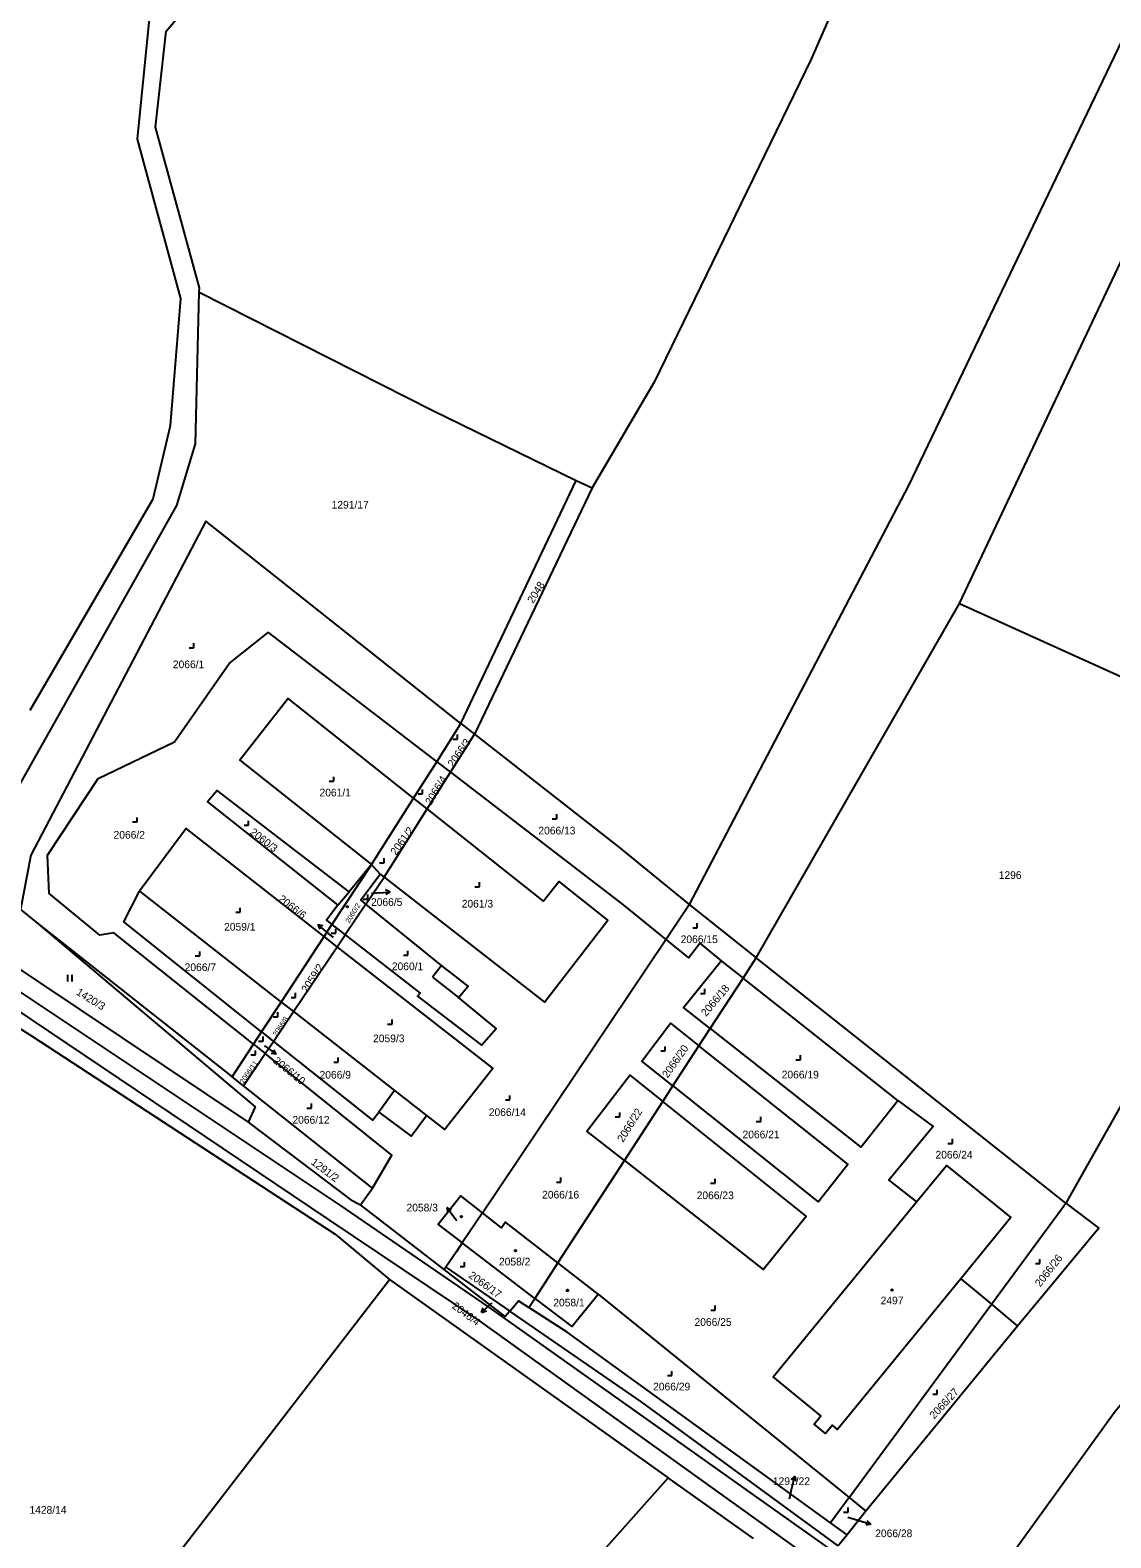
# Model space of a CAD drawing. Extents: x -679220 to -673243, y -1075091 to -1066557.
# Drawn here: x -677836.3 to -677596.9, y -1070402.6 to -1070068.5 of the extents above; entities that cross this region are included whole.
import ezdxf

# ---------------------------------------------------------------- set-up
doc = ezdxf.new("R2010")
doc.units = 0
for name, color, linetype in [('Hranice parcel', 7, 'Continuous'), ('Parcelní čísla', 7, 'Continuous'), ('Pop  PČ popisy', 7, 'Continuous'), ('Vnitřní kresba', 7, 'Continuous'), ('Značky budov', 7, 'Continuous'), ('Značky kultur', 7, 'Continuous')]:
    doc.layers.add(name, color=color, linetype=linetype)

msp = doc.modelspace()

# ---------------------------------------------------------------- linework, layer by layer
at = {"layer": 'Hranice parcel'}
for p, q in [((-677740.82, -1070222.17), (-677715.32, -1070168.27)), ((-677711.74, -1070169.95), (-677737.84, -1070224.53)), ((-677715.32, -1070168.27), (-677711.74, -1070169.95)), ((-677675.39, -1070274.05), (-677630.39, -1070195.53)), ((-677630.39, -1070195.53), (-677551.97, -1070231.11)), ((-677746.2, -1070230.63), (-677740.82, -1070222.17)), ((-677740.82, -1070222.17), (-677737.84, -1070224.53)), ((-677743.16, -1070232.96), (-677737.84, -1070224.53)), ((-677751.31, -1070238.67), (-677746.2, -1070230.63)), ((-677746.2, -1070230.63), (-677743.16, -1070232.96)), ((-677748.29, -1070241.07), (-677743.16, -1070232.96)), ((-677551.97, -1070231.11), (-677606.83, -1070328.42)), ((-677760.67, -1070253.39), (-677751.31, -1070238.67)), ((-677748.29, -1070241.07), (-677751.31, -1070238.67)), ((-677757.85, -1070256.21), (-677748.29, -1070241.07)), ((-677760.67, -1070253.39), (-677769.4, -1070266.7)), ((-677758.72, -1070255.53), (-677760.67, -1070253.39)), ((-677761.86, -1070262.16), (-677757.85, -1070256.21)), ((-677758.72, -1070255.53), (-677757.85, -1070256.21)), ((-677812.04, -1070259.33), (-677780.65, -1070283.87)), ((-677838.43, -1070263.34), (-677834.96, -1070266.14)), ((-677761.86, -1070262.16), (-677766.46, -1070268.99)), ((-677695.46, -1070269.98), (-677690.28, -1070262.25)), ((-677690.28, -1070262.25), (-677675.39, -1070274.05)), ((-677834.96, -1070266.14), (-677791.54, -1070300.48)), ((-677771.13, -1070269.34), (-677769.4, -1070266.7)), ((-677769.4, -1070266.7), (-677766.46, -1070268.99)), ((-677847.48, -1070270.67), (-677787.98, -1070310.51)), ((-677780.65, -1070283.87), (-677771.13, -1070269.34)), ((-677768.23, -1070271.61), (-677771.13, -1070269.34)), ((-677768.23, -1070271.61), (-677766.46, -1070268.99)), ((-677736.08, -1070330.58), (-677695.46, -1070269.98)), ((-677777.93, -1070286), (-677768.23, -1070271.61)), ((-677678.31, -1070278.55), (-677675.39, -1070274.05)), ((-677606.83, -1070328.42), (-677675.39, -1070274.05)), ((-677683.17, -1070274.71), (-677678.31, -1070278.55)), ((-677685.6, -1070289.77), (-677678.31, -1070278.55)), ((-677644.02, -1070305.7), (-677678.31, -1070278.55)), ((-677784.99, -1070290.48), (-677780.65, -1070283.87)), ((-677780.65, -1070283.87), (-677777.93, -1070286)), ((-677782.37, -1070292.58), (-677777.93, -1070286)), ((-677786.8, -1070293.24), (-677784.99, -1070290.48)), ((-677784.99, -1070290.48), (-677782.37, -1070292.58)), ((-677688.09, -1070293.59), (-677685.6, -1070289.77)), ((-677791.54, -1070300.48), (-677786.8, -1070293.24)), ((-677786.8, -1070293.24), (-677784.21, -1070295.31)), ((-677784.21, -1070295.31), (-677782.37, -1070292.58)), ((-677693.85, -1070302.46), (-677688.09, -1070293.59)), ((-677789.03, -1070302.47), (-677784.21, -1070295.31)), ((-677789.03, -1070302.47), (-677791.54, -1070300.48)), ((-677760.41, -1070325.11), (-677789.03, -1070302.47)), ((-677696.09, -1070305.92), (-677693.85, -1070302.46)), ((-677704.6, -1070319.01), (-677696.09, -1070305.92)), ((-677719.33, -1070341.67), (-677704.6, -1070319.01)), ((-677763.09, -1070328.78), (-677760.41, -1070325.11)), ((-677744.51, -1070343.17), (-677763.09, -1070328.78)), ((-677736.08, -1070330.58), (-677740.53, -1070337.23)), ((-677623.32, -1070350.84), (-677606.83, -1070328.42)), ((-677724.43, -1070349.53), (-677740.53, -1070337.23)), ((-677744.15, -1070342.63), (-677744.51, -1070343.17)), ((-677744.15, -1070342.63), (-677730.02, -1070352.35)), ((-677719.33, -1070341.67), (-677724.43, -1070349.53)), ((-677710.43, -1070348.59), (-677719.33, -1070341.67)), ((-677756.66, -1070345.34), (-677694.91, -1070389.28)), ((-677630.06, -1070345.2), (-677623.32, -1070350.84)), ((-677725.76, -1070351.58), (-677724.43, -1070349.53)), ((-677710.43, -1070348.59), (-677654.8, -1070393.66)), ((-677654.8, -1070393.66), (-677623.32, -1070350.84)), ((-677623.32, -1070350.84), (-677617.53, -1070355.69)), ((-677617.53, -1070355.69), (-677651.1, -1070396.66)), ((-677676.01, -1070402.73), (-677694.91, -1070389.28)), ((-677654.8, -1070393.66), (-677658.94, -1070399.28)), ((-677654.8, -1070393.66), (-677651.1, -1070396.66)), ((-677651.1, -1070396.66), (-677655.29, -1070401.92)), ((-677655.29, -1070401.92), (-677658.94, -1070399.28)), ((-677655.29, -1070401.92), (-677657.23, -1070404.36))]:
    msp.add_line(p, q, dxfattribs=at)
for points in [[(-677543.22, -1069801.15), (-677561, -1069854.23), (-677585.31, -1069913.19), (-677593.86, -1069910.68), (-677623.04, -1069982.87), (-677663.22, -1070074.94), (-677697.99, -1070146.52), (-677711.74, -1070169.95)], [(-677490.38, -1069845.96), (-677541.96, -1069957.49), (-677593.5, -1070068.97), (-677641.71, -1070169.41), (-677690.28, -1070262.25)], [(-677630.39, -1070195.53), (-677551.44, -1070028.23), (-677472.53, -1069860.87)], [(-677798.79, -1070126.56), (-677798.76, -1070125.62), (-677808.5, -1070090.03), (-677806.15, -1070068.7), (-677792.35, -1070052.45), (-677770.15, -1070042.36), (-677752.85, -1070019.77), (-677734.25, -1070000.71)], [(-677836.26, -1070219.22), (-677809.01, -1070172.38), (-677805.17, -1070156.15), (-677802.89, -1070127.98), (-677812.51, -1070092.7), (-677809.68, -1070064.56), (-677797.85, -1070049.79)], [(-677594.18, -1070422.35), (-677617.99, -1070405.1), (-677595.86, -1070374.56), (-677562.79, -1070334.89), (-677527.98, -1070275.97), (-677483.78, -1070192.17), (-677443.31, -1070109.44)], [(-677845.88, -1070257.33), (-677841.59, -1070241.09), (-677803.79, -1070173.83), (-677799.59, -1070160.2), (-677798.79, -1070126.56)], [(-677798.79, -1070126.56), (-677747.07, -1070152.8), (-677715.32, -1070168.27)], [(-677740.82, -1070222.17), (-677797.35, -1070177.34), (-677836.07, -1070251.29), (-677838.43, -1070263.34)], [(-677786.8, -1070293.24), (-677817.7, -1070268.5), (-677820.8, -1070269.02), (-677832.08, -1070259.81), (-677832.44, -1070251.36), (-677821.18, -1070234.37), (-677804.26, -1070226.2), (-677792.15, -1070208.89), (-677783.5, -1070201.99), (-677746.2, -1070230.63)], [(-677751.31, -1070238.67), (-677779.09, -1070216.59), (-677789.8, -1070230.31), (-677760.67, -1070253.39)], [(-677737.84, -1070224.53), (-677705.92, -1070249.49), (-677690.28, -1070262.25)], [(-677743.16, -1070232.96), (-677704.89, -1070262.34), (-677695.46, -1070269.98)], [(-677760.67, -1070253.39), (-677765.6, -1070259.46), (-677794.81, -1070237), (-677797, -1070239.48), (-677768.1, -1070262.37), (-677770.62, -1070265.74), (-677769.4, -1070266.7)], [(-677757.85, -1070256.21), (-677722.34, -1070283.91), (-677708.3, -1070265.7), (-677719.04, -1070257.16), (-677722.52, -1070261.55), (-677748.29, -1070241.07)], [(-677771.13, -1070269.34), (-677801.68, -1070245.45), (-677812.04, -1070259.33)], [(-677761.86, -1070262.16), (-677763.01, -1070261.22), (-677758.72, -1070255.53)], [(-677784.99, -1070290.48), (-677815.48, -1070266.13), (-677812.04, -1070259.33)], [(-677766.46, -1070268.99), (-677749.87, -1070281.92), (-677750.44, -1070282.56), (-677736.26, -1070293.4), (-677733.02, -1070289.75), (-677741.36, -1070282.88), (-677739.24, -1070280.32), (-677745.12, -1070275.77), (-677761.86, -1070262.16)], [(-677834.96, -1070266.14), (-677786.4, -1070307.1), (-677787.98, -1070310.51)], [(-677695.46, -1070269.98), (-677690.42, -1070274.07), (-677687.91, -1070270.83), (-677683.17, -1070274.71)], [(-677759.04, -1070308.25), (-677751.86, -1070313.6), (-677748.42, -1070309.02), (-677744.43, -1070312.11), (-677733.78, -1070298.56), (-677768.23, -1070271.61)], [(-677685.6, -1070289.77), (-677691.55, -1070285.09), (-677683.17, -1070274.71)], [(-677777.93, -1070286), (-677755.54, -1070303.5), (-677759.04, -1070308.25)], [(-677838.54, -1070289.74), (-677835.99, -1070291.35), (-677768.72, -1070335.34), (-677756.66, -1070345.34)], [(-677693.85, -1070302.46), (-677700.76, -1070296.95), (-677694.4, -1070288.57), (-677688.09, -1070293.59)], [(-677685.6, -1070289.77), (-677652.21, -1070316.03), (-677644.02, -1070305.7)], [(-677782.37, -1070292.58), (-677760.44, -1070310.08), (-677759.04, -1070308.25)], [(-677693.85, -1070302.46), (-677661.72, -1070328.14), (-677655.11, -1070319.79), (-677688.09, -1070293.59)], [(-677760.41, -1070325.11), (-677756.13, -1070317.8), (-677784.21, -1070295.31)], [(-677704.6, -1070319.01), (-677712.94, -1070312.46), (-677703.38, -1070300.09), (-677696.09, -1070305.92)], [(-677704.6, -1070319.01), (-677673.88, -1070343.14), (-677664.33, -1070331.33), (-677696.09, -1070305.92)], [(-677644.02, -1070305.7), (-677636.23, -1070311.47), (-677646.02, -1070323.34), (-677639.94, -1070328.12)], [(-677787.98, -1070310.51), (-677765.22, -1070327.73), (-677763.09, -1070328.78)], [(-677639.94, -1070328.12), (-677633.25, -1070320.07), (-677619.03, -1070331.62), (-677630.06, -1070345.2)], [(-677736.08, -1070330.58), (-677740.87, -1070326.82), (-677745.88, -1070333.14), (-677740.53, -1070337.23)], [(-677719.33, -1070341.67), (-677730.92, -1070332.66), (-677731.87, -1070333.88), (-677736.08, -1070330.58)], [(-677630.06, -1070345.2), (-677657.41, -1070378.57), (-677658.53, -1070377.65), (-677660.05, -1070379.51), (-677662.6, -1070377.42), (-677661.09, -1070375.57), (-677671.65, -1070366.95), (-677639.94, -1070328.12)], [(-677606.83, -1070328.42), (-677599.53, -1070334.01), (-677617.53, -1070355.69)], [(-677740.53, -1070337.23), (-677741.91, -1070339.28), (-677744.15, -1070342.63)], [(-677730.02, -1070352.35), (-677731.06, -1070353.58), (-677744.51, -1070343.17)], [(-677872.51, -1070491.13), (-677805.2, -1070408.28), (-677756.66, -1070345.34)], [(-677730.02, -1070352.35), (-677728.1, -1070350.07), (-677725.76, -1070351.58)], [(-677724.43, -1070349.53), (-677716.27, -1070355.77), (-677710.43, -1070348.59)], [(-677657.23, -1070404.36), (-677700.73, -1070372.5), (-677730.02, -1070352.35)], [(-677658.94, -1070399.28), (-677717.26, -1070357.04), (-677725.76, -1070351.58)], [(-677694.91, -1070389.28), (-677746.88, -1070447.72), (-677793.45, -1070507.65), (-677841.24, -1070572.65)]]:
    msp.add_lwpolyline(points, dxfattribs=at)
at = {"layer": 'Pop  PČ popisy'}
for p, q in [((-677760.63, -1070259.71), (-677759.48, -1070259.65)), ((-677759.48, -1070259.65), (-677756.48, -1070259.49)), ((-677756.48, -1070259.49), (-677757.51, -1070259.04)), ((-677756.48, -1070259.49), (-677757.46, -1070260.04)), ((-677770.22, -1070268.59), (-677772.52, -1070266.66)), ((-677772.52, -1070266.66), (-677771.43, -1070266.92)), ((-677772.52, -1070266.66), (-677772.07, -1070267.69)), ((-677769.07, -1070269.55), (-677770.22, -1070268.59)), ((-677784.31, -1070293.58), (-677784.18, -1070293.67)), ((-677784.18, -1070293.67), (-677781.75, -1070295.43)), ((-677781.75, -1070295.43), (-677782.86, -1070295.25)), ((-677781.75, -1070295.43), (-677782.27, -1070294.44)), ((-677742.16, -1070331.81), (-677743.97, -1070329.41)), ((-677743.97, -1070329.41), (-677742.96, -1070329.91)), ((-677743.97, -1070329.41), (-677743.76, -1070330.51)), ((-677741.76, -1070332.34), (-677742.16, -1070331.81)), ((-677734.09, -1070350.57), (-677736.25, -1070352.66)), ((-677734.04, -1070350.53), (-677734.09, -1070350.57)), ((-677736.25, -1070352.66), (-677735.88, -1070351.6)), ((-677736.25, -1070352.66), (-677735.18, -1070352.32)), ((-677666.89, -1070388.95), (-677667.6, -1070389.81)), ((-677667.56, -1070391.87), (-677666.89, -1070388.95)), ((-677666.89, -1070388.95), (-677666.62, -1070390.03)), ((-677668.04, -1070393.93), (-677667.56, -1070391.87)), ((-677655.15, -1070398.02), (-677652.92, -1070398.71)), ((-677652.92, -1070398.71), (-677650.05, -1070399.59)), ((-677650.05, -1070399.59), (-677651.15, -1070399.77)), ((-677650.05, -1070399.59), (-677650.86, -1070398.82))]:
    msp.add_line(p, q, dxfattribs=at)
at = {"layer": 'Vnitřní kresba'}
for p, q in [((-677768.1, -1070262.37), (-677765.6, -1070259.46)), ((-677745.12, -1070275.77), (-677747.14, -1070278.39)), ((-677767.61, -1070328.87), (-677841.98, -1070279.26)), ((-677747.14, -1070278.39), (-677741.36, -1070282.88)), ((-677770.23, -1070331.96), (-677843.71, -1070282.56)), ((-677755.54, -1070303.5), (-677748.42, -1070309.02)), ((-677734.73, -1070351.38), (-677767.61, -1070328.87)), ((-677736.82, -1070354.41), (-677770.23, -1070331.96)), ((-677659.05, -1070405.13), (-677734.73, -1070351.38)), ((-677661.76, -1070408.27), (-677736.82, -1070354.41))]:
    msp.add_line(p, q, dxfattribs=at)
at = {"layer": 'Značky budov'}
for centre in [(-677765.97, -1070262.72), (-677740.76, -1070331.44), (-677728.74, -1070338.97), (-677645.31, -1070347.68), (-677717.21, -1070347.78)]:
    msp.add_circle(centre, 0.175, dxfattribs=at)
at = {"layer": 'Značky kultur'}
for p, q in [((-677801.02, -1070205.38), (-677800.02, -1070205.38)), ((-677800.02, -1070205.38), (-677800.02, -1070204.38)), ((-677742.62, -1070225.61), (-677741.62, -1070225.61)), ((-677741.62, -1070225.61), (-677741.62, -1070224.61)), ((-677768.98, -1070234.94), (-677768.98, -1070233.94)), ((-677769.98, -1070234.94), (-677768.98, -1070234.94)), ((-677749.31, -1070237.75), (-677749.31, -1070236.75)), ((-677750.31, -1070237.75), (-677749.31, -1070237.75)), ((-677813.58, -1070243.96), (-677812.58, -1070243.96)), ((-677812.58, -1070243.96), (-677812.58, -1070242.96)), ((-677787.88, -1070244.69), (-677787.88, -1070243.69)), ((-677720.58, -1070243.26), (-677719.58, -1070243.26)), ((-677719.58, -1070243.26), (-677719.58, -1070242.26)), ((-677788.88, -1070244.69), (-677787.88, -1070244.69)), ((-677758.85, -1070253.02), (-677757.85, -1070253.02)), ((-677757.85, -1070253.02), (-677757.85, -1070252.02)), ((-677736.75, -1070258.32), (-677736.75, -1070257.32)), ((-677761.45, -1070261.04), (-677761.45, -1070260.04)), ((-677737.75, -1070258.32), (-677736.75, -1070258.32)), ((-677790.72, -1070263.99), (-677789.72, -1070263.99)), ((-677789.72, -1070263.99), (-677789.72, -1070262.99)), ((-677762.45, -1070261.04), (-677761.45, -1070261.04)), ((-677688.46, -1070267.43), (-677688.46, -1070266.43)), ((-677769.57, -1070268.63), (-677768.57, -1070268.63)), ((-677768.57, -1070268.63), (-677768.57, -1070267.63)), ((-677689.46, -1070267.43), (-677688.46, -1070267.43)), ((-677799.69, -1070273.64), (-677798.69, -1070273.64)), ((-677798.69, -1070273.64), (-677798.69, -1070272.64)), ((-677753.57, -1070273.49), (-677752.57, -1070273.49)), ((-677752.57, -1070273.49), (-677752.57, -1070272.49)), ((-677827.92, -1070279.33), (-677827.92, -1070277.83)), ((-677826.92, -1070279.33), (-677826.92, -1070277.83)), ((-677778.44, -1070282.86), (-677777.44, -1070282.86)), ((-677777.44, -1070282.86), (-677777.44, -1070281.86)), ((-677687.76, -1070281.95), (-677686.76, -1070281.95)), ((-677686.76, -1070281.95), (-677686.76, -1070280.95)), ((-677782.39, -1070287.15), (-677781.39, -1070287.15)), ((-677781.39, -1070287.15), (-677781.39, -1070286.15)), ((-677757.09, -1070288.77), (-677756.09, -1070288.77)), ((-677756.09, -1070288.77), (-677756.09, -1070287.77)), ((-677785.64, -1070292.51), (-677784.64, -1070292.51)), ((-677784.64, -1070292.51), (-677784.64, -1070291.51)), ((-677695.56, -1070294.69), (-677695.56, -1070293.69)), ((-677787.34, -1070295.58), (-677786.34, -1070295.58)), ((-677786.34, -1070295.58), (-677786.34, -1070294.58)), ((-677768.99, -1070297.16), (-677767.99, -1070297.16)), ((-677767.99, -1070297.16), (-677767.99, -1070296.16)), ((-677696.56, -1070294.69), (-677695.56, -1070294.69)), ((-677666.61, -1070296.67), (-677665.61, -1070296.67)), ((-677665.61, -1070296.67), (-677665.61, -1070295.67)), ((-677774.95, -1070307.37), (-677773.95, -1070307.37)), ((-677773.95, -1070307.37), (-677773.95, -1070306.37)), ((-677730.97, -1070305.57), (-677729.97, -1070305.57)), ((-677729.97, -1070305.57), (-677729.97, -1070304.57)), ((-677706.66, -1070309.33), (-677705.66, -1070309.33)), ((-677705.66, -1070309.33), (-677705.66, -1070308.33)), ((-677675.42, -1070310.34), (-677674.42, -1070310.34)), ((-677674.42, -1070310.34), (-677674.42, -1070309.34)), ((-677632.93, -1070315.19), (-677631.93, -1070315.19)), ((-677631.93, -1070315.19), (-677631.93, -1070314.19)), ((-677719.69, -1070323.75), (-677718.69, -1070323.75)), ((-677718.69, -1070323.75), (-677718.69, -1070322.75)), ((-677685.54, -1070324.02), (-677684.54, -1070324.02)), ((-677684.54, -1070324.02), (-677684.54, -1070323.02)), ((-677612.56, -1070341.84), (-677612.56, -1070340.84)), ((-677741, -1070342.51), (-677740, -1070342.51)), ((-677740, -1070342.51), (-677740, -1070341.51)), ((-677613.56, -1070341.84), (-677612.56, -1070341.84)), ((-677685.48, -1070352.13), (-677684.48, -1070352.13)), ((-677684.48, -1070352.13), (-677684.48, -1070351.13)), ((-677695.09, -1070366.64), (-677694.09, -1070366.64)), ((-677694.09, -1070366.64), (-677694.09, -1070365.64)), ((-677636.31, -1070370.77), (-677635.31, -1070370.77)), ((-677635.31, -1070370.77), (-677635.31, -1070369.77)), ((-677656.05, -1070396.88), (-677655.05, -1070396.88)), ((-677655.05, -1070396.88), (-677655.05, -1070395.88))]:
    msp.add_line(p, q, dxfattribs=at)

# ---------------------------------------------------------------- texts
at = {"layer": 'Parcelní čísla'}
for s, p in [('1291/17', (-677769.47, -1070174.53)), ('2066/1', (-677804.64, -1070209.89)), ('2061/1', (-677772.15, -1070238.3)), ('2066/2', (-677817.78, -1070247.67)), ('2066/13', (-677723.67, -1070246.73)), ('1296', (-677621.69, -1070256.59)), ('2066/5', (-677760.75, -1070262.57)), ('2061/3', (-677740.65, -1070262.93)), ('2059/1', (-677793.29, -1070268.05)), ('2066/15', (-677692.15, -1070270.81)), ('2066/7', (-677802.03, -1070277.01)), ('2060/1', (-677756.13, -1070276.81)), ('2059/3', (-677760.29, -1070292.78)), ('2066/9', (-677772.15, -1070300.83)), ('2066/19', (-677669.76, -1070300.8)), ('2066/14', (-677734.65, -1070309.13)), ('2066/12', (-677778.15, -1070310.82)), ('2066/21', (-677678.45, -1070314.06)), ('2066/24', (-677635.7, -1070318.55)), ('2066/16', (-677722.85, -1070327.41)), ('2066/23', (-677688.6, -1070327.55)), ('2058/3', (-677752.88, -1070330.27)), ('2058/2', (-677732.4, -1070342.24)), ('2058/1', (-677720.37, -1070351.32)), ('2497', (-677647.85, -1070350.85)), ('2066/25', (-677689.08, -1070355.63)), ('2066/29', (-677698.25, -1070369.93)), ('1291/22', (-677671.72, -1070390.9)), ('1428/14', (-677836.42, -1070397.27)), ('2066/28', (-677649.05, -1070402.45))]:
    msp.add_text(s, height=1.7, dxfattribs=at).set_placement(p)
for s, height, rotation, p in [('2048', 1.7, 58, (-677724.83, -1070195.67)), ('2066/3', 1.7, 55, (-677742.53, -1070231.94)), ('2066/4', 1.7, 59, (-677747.43, -1070240.35)), ('2060/3', 1.7, 322, (-677787.73, -1070246.51)), ('2061/2', 1.7, 54, (-677755.23, -1070251.46)), ('2066/6', 1.7, 322, (-677781.41, -1070261.32)), ('2060/2', 1.14, 58, (-677765.57, -1070266.51)), ('2059/2', 1.7, 57, (-677774.9, -1070281.94)), ('2066/18', 1.7, 50, (-677686.5, -1070287.19)), ('1420/3', 1.7, 328, (-677826.2, -1070282.1)), ('2066/8', 1.14, 56, (-677781.68, -1070291.58)), ('2066/20', 1.7, 55, (-677695.02, -1070300.84)), ('2066/11', 1.14, 56, (-677788.97, -1070302.07)), ('2066/10', 1.7, 321, (-677782.55, -1070297.17)), ('2066/22', 1.7, 58, (-677704.9, -1070315.07)), ('1291/2', 1.7, 323, (-677774.19, -1070319.68)), ('2066/26', 1.7, 52, (-677612.5, -1070347.11)), ('2066/17', 1.7, 324, (-677739.28, -1070344.76)), ('2046/4', 1.7, 323, (-677742.94, -1070351.54)), ('2066/27', 1.7, 47, (-677635.99, -1070376.39))]:
    msp.add_text(s, height=height, rotation=rotation, dxfattribs=at).set_placement(p)

doc.saveas('drawing.dxf')
